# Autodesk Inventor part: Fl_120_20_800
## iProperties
Created: 2008-03
Part Number: Fl_120_20_800
Material: S 235 JR
Document SubType Name: Modeling
Designer: bts
Density: 7.85 g/cm^3
Mass: 26187.6 g
Surface Area: 3940 cm^2
Volume: 3336 cm^3
Author: bts
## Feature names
1. Extrusion1
